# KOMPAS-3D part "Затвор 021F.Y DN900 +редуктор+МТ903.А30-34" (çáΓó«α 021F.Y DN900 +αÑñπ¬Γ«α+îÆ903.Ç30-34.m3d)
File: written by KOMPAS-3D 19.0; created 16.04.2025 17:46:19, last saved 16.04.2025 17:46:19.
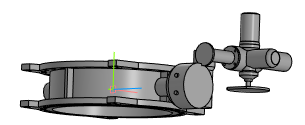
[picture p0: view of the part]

Document properties: Полное имя файла: Затвор 021F.Y DN900 +редуктор+МТ903.А30-34.a3d

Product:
- Part/product: Затвор 021F.Y DN900 +редуктор+МТ903.А30-34
    Масса: 938.078

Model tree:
1. Операция без истории:1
